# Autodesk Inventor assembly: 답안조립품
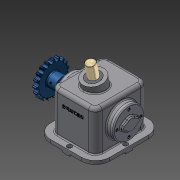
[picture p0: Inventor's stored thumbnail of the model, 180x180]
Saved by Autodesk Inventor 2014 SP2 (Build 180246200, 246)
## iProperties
Created: 2014-11
Part Number: 답안조립품
Document SubType Name: Assembly
Designer: 201-07
Author: 201-07
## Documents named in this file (13)
- C:\Users\201-07\Desktop\441122v1014\답안조립품.iam
- C:\Users\201-07\Desktop\441122v1014\5-체인 스프로킷.ipt
- C:\Users\201-07\Desktop\441122v1014\M4x0.5.ipt
- C:\Users\201-07\Desktop\441122v1014\답안부품.ipt
- C:\Users\201-07\Desktop\441122v1014\뒤커버.ipt
- C:\Users\201-07\Desktop\441122v1014\멈춤나사 M5x0.5.ipt
- C:\Users\201-07\Desktop\441122v1014\베어링 6205.ipt
- C:\Users\201-07\Desktop\441122v1014\부시.ipt
- C:\Users\201-07\Desktop\441122v1014\슬라이드.ipt
- C:\Users\201-07\Desktop\441122v1014\앞커버.ipt
- C:\Users\201-07\Desktop\441122v1014\오일실.ipt
- C:\Users\201-07\Desktop\441122v1014\키 8x8.ipt
- C:\Users\201-07\Desktop\441122v1014\편심축.ipt
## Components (9 placed, 2 different names)
1. 5-체인 스프로킷:1 — 각도:1, 플러쉬:3
2. M4x0.5:5
3. M4x0.5:6
4. M4x0.5:7
5. M4x0.5:8
6. M4x0.5:1
7. M4x0.5:2
8. M4x0.5:3
9. M4x0.5:4
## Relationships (2: Angle 1, Flush 1)
- 각도:1 [Angle]: 5-체인 스프로킷:1
- 플러쉬:3 [Flush]: 5-체인 스프로킷:1
